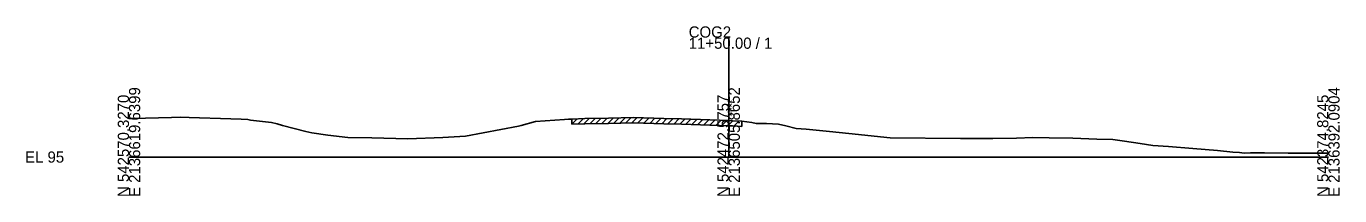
# Model space of a CAD drawing. Extents: x -13397 to 2303, y -10 to 39059.
# Drawn here: x -25.7 to 302.8, y 2990.3 to 3032.8 of the extents above; entities that cross this region are included whole.
import ezdxf

# ---------------------------------------------------------------- set-up
doc = ezdxf.new("R2010")
doc.units = 0
for name, color, linetype in [('RD_GPK_XS_Cell', 7, 'Continuous'), ('RD_XS_ExGround', 7, 'Continuous'), ('RD_XS_ExPaveRet', 7, 'Continuous'), ('RD_XS_TX_Elev_EX', 7, 'Continuous')]:
    doc.layers.add(name, color=color, linetype=linetype)

msp = doc.modelspace()

# ---------------------------------------------------------------- linework, layer by layer
at = {"layer": 'RD_GPK_XS_Cell'}
for p, q in [((150, 3000), (150, 3029.91)), ((0, 3000), (150, 3000)), ((150, 3000), (300, 3000))]:
    msp.add_line(p, q, dxfattribs=at)
at = {"layer": 'RD_XS_ExGround'}
for p, q in [((0, 3009.64), (0.87, 3009.66)), ((0.87, 3009.66), (10.65, 3009.92)), ((10.65, 3009.92), (12.91, 3009.97)), ((12.91, 3009.97), (15.05, 3009.9)), ((15.05, 3009.9), (25.48, 3009.54)), ((25.48, 3009.54), (28.05, 3009.5)), ((28.05, 3009.5), (29.76, 3009.37)), ((29.76, 3009.37), (30.39, 3009.26)), ((101.72, 3008.86), (108.9, 3009.37)), ((108.9, 3009.37), (109.96, 3009.45)), ((109.96, 3009.45), (110.78, 3009.52)), ((110.78, 3009.52), (113.99, 3009.61)), ((113.99, 3009.61), (119.95, 3009.74)), ((119.95, 3009.74), (126.21, 3009.88)), ((126.21, 3009.88), (133.75, 3009.62)), ((133.75, 3009.62), (138.21, 3009.53)), ((138.21, 3009.53), (142.96, 3009.38)), ((142.96, 3009.38), (150, 3009.12)), ((30.39, 3009.26), (35.68, 3008.63)), ((35.68, 3008.63), (37.1, 3008.29)), ((37.1, 3008.29), (38.4, 3007.88)), ((38.4, 3007.88), (44.25, 3006.39)), ((44.25, 3006.39), (45.73, 3006.08)), ((45.73, 3006.08), (49.74, 3005.5)), ((84.17, 3005.24), (97.46, 3007.77)), ((97.46, 3007.77), (98.09, 3007.89)), ((98.09, 3007.89), (101.72, 3008.86)), ((150, 3009.12), (150.97, 3009.08)), ((150.97, 3009.08), (153.31, 3008.98)), ((153.31, 3008.98), (155.78, 3008.61)), ((155.78, 3008.61), (156.85, 3008.44)), ((156.85, 3008.44), (159.48, 3008.36)), ((159.48, 3008.36), (162.44, 3008.25)), ((162.44, 3008.25), (164.33, 3007.79)), ((164.33, 3007.79), (166.85, 3007.17)), ((166.85, 3007.17), (169.4, 3006.95)), ((169.4, 3006.95), (175.21, 3006.4)), ((175.21, 3006.4), (180.04, 3005.86)), ((49.74, 3005.5), (54.72, 3004.93)), ((54.72, 3004.93), (60.72, 3004.77)), ((60.72, 3004.77), (69.73, 3004.59)), ((69.73, 3004.59), (78.49, 3004.91)), ((78.49, 3004.91), (84.17, 3005.24)), ((180.04, 3005.86), (190.39, 3004.79)), ((190.39, 3004.79), (207.95, 3004.64)), ((207.95, 3004.64), (216.09, 3004.64)), ((216.09, 3004.64), (222.02, 3004.73)), ((222.02, 3004.73), (226.09, 3004.86)), ((226.09, 3004.86), (230.13, 3004.8)), ((230.13, 3004.8), (236.09, 3004.75)), ((236.09, 3004.75), (242.08, 3004.45)), ((242.08, 3004.45), (246.09, 3004.42)), ((246.09, 3004.42), (248.97, 3003.95)), ((248.97, 3003.95), (252.89, 3003.41)), ((252.89, 3003.41), (256.09, 3002.87)), ((256.09, 3002.87), (259.99, 3002.6)), ((259.99, 3002.6), (266.09, 3002.12)), ((266.09, 3002.12), (272.3, 3001.63)), ((272.3, 3001.63), (276.09, 3001.24)), ((276.09, 3001.24), (277.81, 3001.12)), ((277.81, 3001.12), (278.93, 3001)), ((278.93, 3001), (280.52, 3001.03)), ((280.52, 3001.03), (284, 3001.06)), ((284, 3001.06), (289.93, 3001)), ((289.93, 3001), (300, 3001))]:
    msp.add_line(p, q, dxfattribs=at)
at = {"layer": 'RD_XS_ExPaveRet'}
for p, q in [((110.78, 3008.22), (112.12, 3009.56)), ((110.78, 3008.22), (110.78, 3009.52)), ((112.28, 3008.26), (113.62, 3009.6)), ((113.78, 3008.3), (115.11, 3009.63)), ((115.28, 3008.34), (116.61, 3009.67)), ((116.78, 3008.37), (118.11, 3009.7)), ((118.28, 3008.4), (119.61, 3009.73)), ((119.78, 3008.43), (121.11, 3009.76)), ((121.28, 3008.47), (122.61, 3009.8)), ((122.78, 3008.5), (124.11, 3009.83)), ((124.28, 3008.53), (125.61, 3009.86)), ((125.78, 3008.57), (127.06, 3009.85)), ((127.28, 3008.54), (128.54, 3009.8)), ((128.78, 3008.49), (130.04, 3009.75)), ((130.28, 3008.44), (131.54, 3009.7)), ((131.78, 3008.39), (133.04, 3009.65)), ((133.28, 3008.34), (134.55, 3009.61)), ((134.78, 3008.3), (136.05, 3009.57)), ((136.28, 3008.27), (137.55, 3009.54)), ((137.78, 3008.24), (139.05, 3009.5)), ((139.28, 3008.2), (140.54, 3009.46)), ((140.78, 3008.15), (142.04, 3009.41)), ((142.28, 3008.11), (143.54, 3009.36)), ((110.78, 3008.22), (113.99, 3008.31)), ((113.99, 3008.31), (119.95, 3008.44)), ((119.95, 3008.44), (126.21, 3008.58)), ((126.21, 3008.58), (133.75, 3008.32)), ((133.75, 3008.32), (138.21, 3008.23)), ((138.21, 3008.23), (142.96, 3008.08)), ((142.96, 3008.08), (150, 3007.82)), ((143.78, 3008.05), (145.03, 3009.31)), ((145.28, 3008), (146.53, 3009.25)), ((146.78, 3007.94), (148.03, 3009.19)), ((148.28, 3007.88), (149.53, 3009.14)), ((149.78, 3007.83), (151.03, 3009.08)), ((150, 3007.82), (150.97, 3007.78)), ((150.97, 3007.78), (153.31, 3007.68)), ((151.28, 3007.77), (152.53, 3009.02)), ((153.31, 3008.98), (153.31, 3007.68))]:
    msp.add_line(p, q, dxfattribs=at)

# ---------------------------------------------------------------- texts
at = {"layer": 'RD_GPK_XS_Cell'}
for s, p in [('COG2', (140, 3029.91)), ('11+50.00 / 1', (140, 3027.11)), ('EL 95', (-26, 2998.6))]:
    msp.add_text(s, height=2.8, dxfattribs=at).set_placement(p)
for s, p in [('E 2136619.6399', (2.8, 2990)), ('E 2136505.8652', (152.8, 2990)), ('E 2136392.0904', (302.8, 2990)), ('N 542570.3270', (0, 2990)), ('N 542472.5757', (150, 2990)), ('N 542374.8245', (300, 2990))]:
    msp.add_text(s, height=2.8, rotation=90, dxfattribs=at).set_placement(p)
at = {"layer": 'RD_XS_TX_Elev_EX'}
msp.add_text('104.12', height=1, rotation=90, dxfattribs=at).set_placement((150.75, 3010.12))

doc.saveas('drawing.dxf')
